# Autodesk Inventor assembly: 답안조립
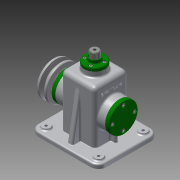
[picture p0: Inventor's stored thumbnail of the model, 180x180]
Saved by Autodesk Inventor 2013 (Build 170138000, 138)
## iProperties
Created: 2016-01
Part Number: 답안조립
Document SubType Name: Assembly
Designer: Administrator
Author: Administrator
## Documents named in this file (19)
- C:\Users\Administrator\Desktop\460127V1008\답안조립.iam
- C:\Users\Administrator\Desktop\460127V1008\본체.ipt
- C:\Users\Administrator\Desktop\460127V1008\V-벨트풀리.ipt
- C:\Users\Administrator\Desktop\460127V1008\고정핀.ipt
- C:\Users\Administrator\Desktop\460127V1008\뒤커버.ipt
- C:\Users\Administrator\Desktop\460127V1008\링크.ipt
- C:\Users\Administrator\Desktop\460127V1008\멈춤링 6 x 5.ipt
- C:\Users\Administrator\Desktop\460127V1008\멈춤링 15 x 1.ipt
- C:\Users\Administrator\Desktop\460127V1008\베어링 15 x 35 x 11.ipt
- C:\Users\Administrator\Desktop\460127V1008\볼트 M3 x 8.ipt
- C:\Users\Administrator\Desktop\460127V1008\볼트 M4 x 10.ipt
- C:\Users\Administrator\Desktop\460127V1008\볼트 M6 x 12.ipt
- C:\Users\Administrator\Desktop\460127V1008\상부부시.ipt
- C:\Users\Administrator\Desktop\460127V1008\슬라이드바.ipt
- C:\Users\Administrator\Desktop\460127V1008\앞커버.ipt
- C:\Users\Administrator\Desktop\460127V1008\오일실 15 25 7.ipt
- C:\Users\Administrator\Desktop\460127V1008\와셔.ipt
- C:\Users\Administrator\Desktop\460127V1008\키 5 x 5 x 14.ipt
- C:\Users\Administrator\Desktop\460127V1008\편심축.ipt
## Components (15 placed, 5 different names)
1. V-벨트풀리:1 — 각도:2
2. 고정핀:1
3. ISO 4018 M6 x 12:1
4. ISO 4762 M4 x 10:1
5. ISO 4762 M4 x 10:3
6. ISO 4762 M4 x 10:4
7. ISO 4762 M4 x 10:5
8. ISO 4762 M4 x 10:2
9. ISO 4762 M4 x 10:6
10. ISO 4762 M4 x 10:7
11. ISO 4762 M4 x 10:8
12. ISO 4762 M3 x 8:1
13. ISO 4762 M3 x 8:2
14. ISO 4762 M3 x 8:3
15. ISO 4762 M3 x 8:4
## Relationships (1: Angle 1)
- 각도:2 [Angle]: V-벨트풀리:1
